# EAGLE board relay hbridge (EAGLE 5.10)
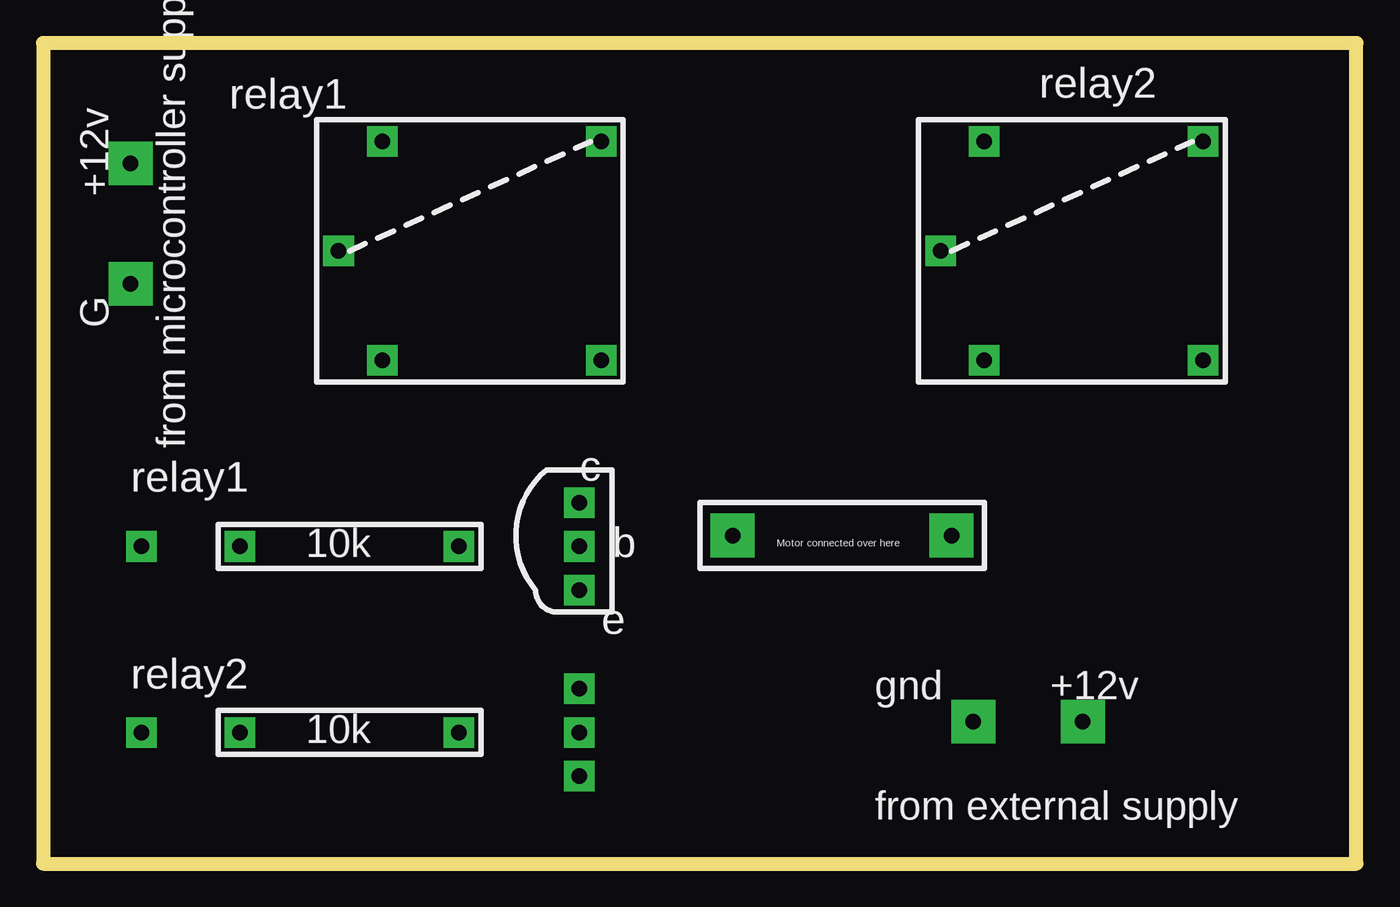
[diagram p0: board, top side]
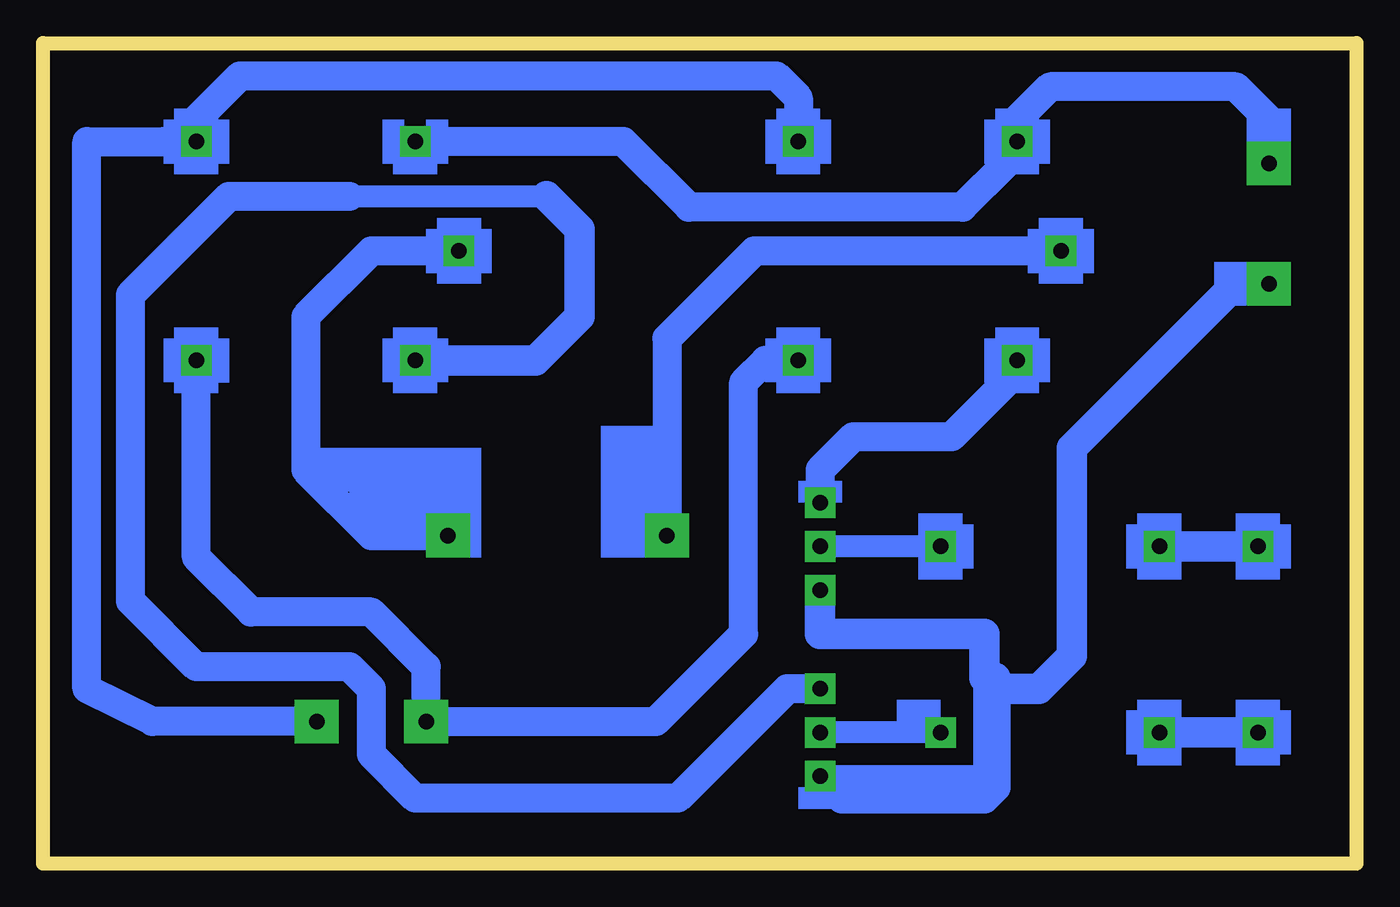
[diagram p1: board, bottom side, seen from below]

Size 76.2 x 47.62 mm. Coordinates in mm from the lower left corner, seen from the top.
Outline: 0,0 76.2,0 76.2,47.62 0,47.62 0,0
Copper layers (1*16): Top 0.035mm / dielectric 1.5mm / Bottom 0.035mm
Design rules "default": minimum track width 10mil, minimum drill 24mil, track to track 8mil, track to pad 8mil, pad to pad 8mil, via to via 8mil, smd to smd 8mil, copper to edge 40mil, drill to drill 8mil, minimum pad ring 10mil, minimum via ring 8mil, stop-mask expansion 4mil, vias tented up to drill 0mil, thermal gap 10mil

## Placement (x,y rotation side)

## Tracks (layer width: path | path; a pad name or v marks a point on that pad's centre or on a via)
S$1  (via drill 0.9 pad 1.78)
  other vias: 54.61,29.21
S$2  (via drill 0.9 pad 1.78)
  other vias: 52.07,35.56
S$3  (via drill 0.9 pad 1.78)
  other vias: 19.68,29.21
S$4  (via drill 0.9 pad 1.78)
  other vias: 19.68,41.91
S$5  (via drill 0.9 pad 1.78)
  other vias: 32.38,29.21
S$6  (via drill 0.9 pad 1.78)
  other vias: 54.61,41.91
S$7  (via drill 0.9 pad 1.78)
  other vias: 67.31,29.21
S$8  (via drill 0.9 pad 1.78)
  other vias: 19.68,29.21
S$9  (via drill 0.9 pad 1.78)
  other vias: 32.38,41.91
S$10  (via drill 0.9 pad 1.78)
  other vias: 19.68,41.91
S$11  (via drill 0.9 pad 1.78)
  other vias: 32.38,29.21
S$12  (via drill 0.9 pad 1.78)
  other vias: 54.61,29.21
S$13  (via drill 0.9 pad 1.78)
  other vias: 67.31,41.91
S$14  (via drill 0.9 pad 1.78)
  other vias: 32.38,41.91
S$15  (via drill 0.9 pad 1.78)
  other vias: 17.14,35.56
S$16
  Bottom 1.676: 18.41,35.56 34.92,35.56 40.01,30.48 40.01,19.68
S$17
  Bottom 1.676: 53.34,35.56 57.15,35.56 60.96,31.75 60.96,22.86 57.15,19.05 53.34,19.05
S$18  (via drill 0.9 pad 1.78)
  other vias: 54.61,41.91
S$19  (via drill 0.9 pad 1.78)
  other vias: 67.31,29.21
S$20
  Bottom 1.676: 60.96,8.26 69.85,8.26 73.66,10.16 73.66,41.91 69.22,41.91
S$21
  Bottom 1.676: 67.31,43.18 64.77,45.72 33.66,45.72 32.38,44.45 32.38,43.18
S$22
  Bottom 1.676: 53.98,8.89 53.98,11.43 57.15,14.61 64.14,14.61 67.31,17.78 67.31,27.94
S$23
  Bottom 1.676: 53.34,8.26 40.64,8.26 35.56,13.34 35.56,27.94 34.29,29.21 33.66,29.21
S$24  (via drill 0.9 pad 1.78)
  other vias: 67.31,41.91
S$25
  Bottom 1.676: 5.08,43.18 6.99,45.09 17.78,45.09 19.68,43.18
S$26
  Bottom 1.676: 20.32,40.64 22.86,38.1 38.73,38.1 42.55,41.91 53.34,41.91
S$27
  Bottom 1.676: 20.32,27.94 23.5,24.77 29.21,24.77 31.11,22.86 31.11,21.59
S$28
  Bottom 1.27: 58.42,38.73 46.99,38.73
  Bottom 1.676: 31.75,10.16 33.02,10.16 39.37,3.81 54.61,3.81 57.15,6.35 57.15,10.16 58.42,11.43 67.31,11.43 71.12,15.24 71.12,33.02 65.41,38.73 58.42,38.73
  Bottom 1.778: 46.99,38.73 45.09,36.83 45.09,31.75 47.62,29.21 53.34,29.21
S$29
  Bottom 1.27: 21.59,13.34 21.59,5.08 30.48,5.08
  Bottom 1.778: 7.62,33.02 16.51,24.13 16.51,12.06 18.41,10.16 20.95,10.16 21.59,10.79 21.59,13.34 31.11,13.34 31.11,15.24
S$30
  Bottom 1.778: 20.95,10.79 20.95,4.45 21.59,3.81 29.84,3.81
S$37  (via drill 0.9 pad 2.54)
  other vias: 40.01,19.05
S$38  (via drill 0.9 pad 2.54)
  other vias: 52.7,19.05
S$39  (via drill 0.9 pad 1.78)
  other vias: 31.11,20.95
S$40  (via drill 0.9 pad 1.78)
  other vias: 31.11,18.41
S$41  (via drill 0.9 pad 1.78)
  other vias: 31.11,15.88
S$42  (via drill 0.9 pad 1.78)
  other vias: 31.11,10.16
S$43  (via drill 0.9 pad 1.78)
  other vias: 31.11,7.62
S$44  (via drill 0.9 pad 1.78)
  other vias: 31.11,5.08
S$51  (via drill 0.9 pad 2.54)
  other vias: 5.08,40.64
S$52  (via drill 0.9 pad 2.54)
  other vias: 5.08,33.66
S$56  (via drill 0.9 pad 1.78)
  other vias: 24.13,18.41
S$57  (via drill 0.9 pad 1.78)
  other vias: 24.13,7.62
S$58  (via drill 0.9 pad 1.78)
  other vias: 11.43,7.62
S$73  (via drill 0.9 pad 2.54)
  other vias: 60.33,8.26
S$74  (via drill 0.9 pad 2.54)
  other vias: 53.98,8.26
S$76  (via drill 0.9 pad 1.78)
  other vias: 11.43,18.41
S$82
  Bottom 1.27: 52.7,35.56 52.7,36.2
S$88
  Bottom 1.27: 24.77,18.41 30.48,18.41
S$89
  Bottom 1.27: 24.77,7.62 30.48,7.62
S$96  (via drill 0.9 pad 1.78)
  other vias: 5.71,18.41
S$97  (via drill 0.9 pad 1.78)
  other vias: 5.71,7.62
S$100
  Bottom 1.27: 10.79,18.41 10.16,18.41
  Bottom 1.778: 6.35,18.41 10.16,18.41
S$101
  Bottom 1.27: 10.79,7.62 10.16,7.62
  Bottom 1.778: 6.35,7.62 10.16,7.62
(copper drawn outside any net)
  shapes: Bottom area x65

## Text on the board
tPlace: Available supply for dc and external is 12v | relay1 | relay2 | +12v | G | from microcontroller supply | relay1 | c | 10k | b | Motor connected over here | e | relay2 | gnd | +12v | 10k | from external supply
